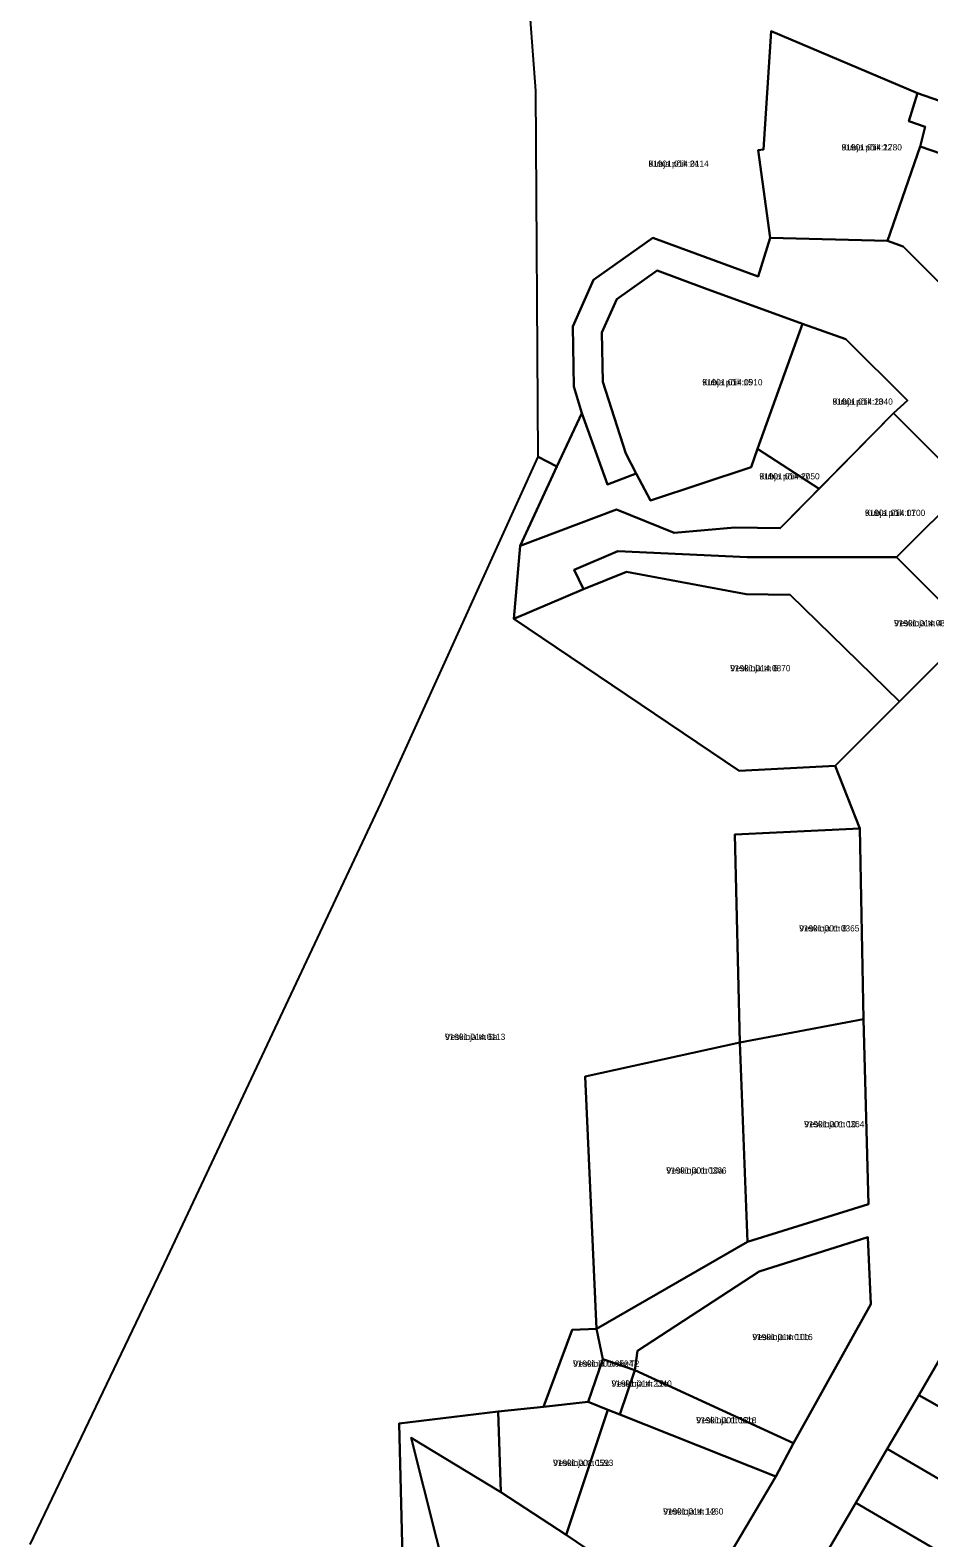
# Model space of a CAD drawing. Extents: x 675810 to 681273, y 6411190 to 6417565.
# Drawn here: x 678176.1 to 678392.3, y 6413180.1 to 6413542.7 of the extents above; entities that cross this region are included whole.
import ezdxf

# ---------------------------------------------------------------- set-up
doc = ezdxf.new("R2010")
doc.units = 0
for name, color, linetype in [('L_AADRESS', 7, 'Continuous'), ('PIIR', 7, 'Continuous'), ('TUNNUS', 7, 'Continuous')]:
    doc.layers.add(name, color=color, linetype=linetype)

msp = doc.modelspace()

# ---------------------------------------------------------------- linework, layer by layer
at = {"layer": 'PIIR'}
for points in [[(678295.76, 6413554.98), (678293.96, 6413581.95), (678477.82, 6413522.85), (678458.5, 6413494.01), (678446.21, 6413498.66), (678451.25, 6413506.22), (678426.9, 6413514.62), (678389.61, 6413527.56), (678354.34, 6413542.49), (678352.55, 6413514.04), (678351.25, 6413513.9), (678354.14, 6413492.79), (678351.28, 6413483.5), (678325.9, 6413492.81), (678311.61, 6413482.73), (678306.63, 6413471.48), (678306.92, 6413457.06), (678308.78, 6413450.62), (678302.83, 6413437.81), (678298.35, 6413440.16), (678297.78, 6413528.19)], [(678389.61, 6413527.56), (678387.5, 6413520.85), (678391.4, 6413519.53), (678390.19, 6413514.73), (678382.36, 6413492.05), (678354.14, 6413492.79), (678351.25, 6413513.9), (678352.55, 6413514.04), (678354.34, 6413542.49)], [(678426.9, 6413514.62), (678417.74, 6413505.28), (678390.19, 6413514.73), (678391.4, 6413519.53), (678387.5, 6413520.85), (678389.61, 6413527.56)], [(678386.16, 6413490.69), (678382.36, 6413492.05), (678390.19, 6413514.73), (678417.74, 6413505.28), (678408.5, 6413496.18), (678394.65, 6413482.21)], [(678338.31, 6413480.67), (678361.93, 6413472.14), (678351.11, 6413442.02), (678349.54, 6413437.63), (678325.34, 6413429.64), (678321.86, 6413436.1), (678319.44, 6413440.92), (678313.89, 6413458.18), (678313.65, 6413470.02), (678317.22, 6413478.07), (678326.94, 6413484.97)], [(678361.93, 6413472.14), (678372.33, 6413468.43), (678387.17, 6413453.67), (678383.8, 6413450.61), (678365.89, 6413432.45), (678351.11, 6413442.02)], [(678384.53, 6413415.96), (678354.7, 6413416.01), (678348.57, 6413416.03), (678317.48, 6413417.46), (678306.94, 6413412.98), (678309.26, 6413408.27), (678292.44, 6413401.19), (678293.98, 6413418.76), (678317.17, 6413427.45), (678331, 6413421.85), (678345.66, 6413423.1), (678356.55, 6413422.98), (678383.8, 6413450.61), (678401.49, 6413432.94)], [(678308.78, 6413450.62), (678314.99, 6413433.46), (678321.86, 6413436.1), (678325.34, 6413429.64), (678349.54, 6413437.63), (678351.11, 6413442.02), (678365.89, 6413432.45), (678356.55, 6413422.98), (678345.66, 6413423.1), (678331, 6413421.85), (678317.17, 6413427.45), (678293.98, 6413418.76), (678302.83, 6413437.81)], [(678402.22, 6413398.29), (678384.53, 6413415.96), (678401.49, 6413432.94), (678419.18, 6413415.28)], [(678348.37, 6413407.11), (678319.56, 6413412.48), (678309.26, 6413408.27), (678306.94, 6413412.98), (678317.48, 6413417.46), (678348.57, 6413416.03), (678354.7, 6413416.01), (678384.53, 6413415.96), (678402.22, 6413398.29), (678385.26, 6413381.3), (678358.97, 6413406.95)], [(678346.64, 6413364.6), (678292.44, 6413401.19), (678309.26, 6413408.27), (678319.56, 6413412.48), (678348.37, 6413407.11), (678358.97, 6413406.95), (678385.26, 6413381.3), (678369.78, 6413365.8)], [(678346.8, 6413299.26), (678345.6, 6413349.27), (678375.7, 6413350.7), (678376.58, 6413304.88)], [(678348.69, 6413251.36), (678346.8, 6413299.26), (678376.58, 6413304.88), (678377.8, 6413260.37)], [(678312.34, 6413230.42), (678309.59, 6413291.13), (678346.8, 6413299.26), (678348.69, 6413251.36)], [(678321.55, 6413220.47), (678322.24, 6413225.13), (678351.48, 6413244.23), (678377.66, 6413252.46), (678378.36, 6413236.35), (678359.77, 6413202.91)], [(678306.53, 6413230.15), (678312.34, 6413230.42), (678313.86, 6413223.09), (678310.38, 6413212.81), (678299.56, 6413211.68)], [(678397.45, 6413227.43), (678427.06, 6413210.73), (678419.68, 6413197.67), (678389.92, 6413214.47)], [(678321.55, 6413220.47), (678317.98, 6413209.79), (678315.07, 6413210.95), (678310.38, 6413212.81), (678313.86, 6413223.09)], [(678359.77, 6413202.91), (678355.48, 6413194.89), (678317.98, 6413209.79), (678321.55, 6413220.47)], [(678288.73, 6413210.5), (678299.56, 6413211.68), (678310.38, 6413212.81), (678315.07, 6413210.95), (678305.06, 6413180.85), (678289.3, 6413191.12)], [(678389.92, 6413214.47), (678419.68, 6413197.67), (678411.67, 6413184.37), (678382.31, 6413201.53)], [(678264.91, 6413207.66), (678288.73, 6413210.5), (678289.3, 6413191.12), (678267.76, 6413204.19), (678282.97, 6413143.7), (678276.6, 6413143.82), (678266.54, 6413143.9), (678266.34, 6413149.86)], [(678335.13, 6413160.53), (678305.06, 6413180.85), (678315.07, 6413210.95), (678317.98, 6413209.79), (678355.48, 6413194.89)], [(678435.46, 6413132.45), (678399.43, 6413154.72), (678395.78, 6413156.89), (678366.24, 6413174.06), (678374.74, 6413188.57), (678404.1, 6413171.42), (678411.67, 6413184.37), (678419.68, 6413197.67), (678427.06, 6413210.73), (678448.79, 6413198.47), (678468.34, 6413187.35)], [(678267.76, 6413204.19), (678289.3, 6413191.12), (678305.06, 6413180.85), (678335.13, 6413160.53), (678321.6, 6413137.39), (678312.36, 6413143.28), (678282.97, 6413143.7)], [(678382.31, 6413201.53), (678411.67, 6413184.37), (678404.1, 6413171.42), (678374.74, 6413188.57)]]:
    msp.add_lwpolyline(points, close=True, dxfattribs=at)
for points in [[(678401.49, 6413432.94), (678383.8, 6413450.61), (678387.17, 6413453.67), (678372.33, 6413468.43), (678361.93, 6413472.14), (678338.31, 6413480.67), (678326.94, 6413484.97), (678317.22, 6413478.07), (678313.65, 6413470.02), (678313.89, 6413458.18), (678319.44, 6413440.92), (678321.86, 6413436.1), (678314.99, 6413433.46), (678308.78, 6413450.62), (678306.92, 6413457.06), (678306.63, 6413471.48), (678311.61, 6413482.73), (678325.9, 6413492.81), (678351.28, 6413483.5), (678354.14, 6413492.79), (678382.36, 6413492.05), (678386.16, 6413490.69), (678394.65, 6413482.21)], [(678176.1, 6413178.55), (678207.8, 6413244.78), (678260.44, 6413356.78), (678298.35, 6413440.16), (678302.83, 6413437.81), (678293.98, 6413418.76), (678292.44, 6413401.19), (678346.64, 6413364.6), (678369.78, 6413365.8), (678375.7, 6413350.7), (678345.6, 6413349.27), (678346.8, 6413299.26), (678309.59, 6413291.13), (678312.34, 6413230.42), (678306.53, 6413230.15), (678299.56, 6413211.68), (678288.73, 6413210.5), (678264.91, 6413207.66), (678266.34, 6413149.86)], [(678335.13, 6413160.53), (678355.48, 6413194.89), (678359.77, 6413202.91), (678378.36, 6413236.35), (678377.66, 6413252.46), (678351.48, 6413244.23), (678322.24, 6413225.13), (678321.55, 6413220.47), (678313.86, 6413223.09), (678312.34, 6413230.42), (678348.69, 6413251.36), (678377.8, 6413260.37), (678376.58, 6413304.88), (678375.7, 6413350.7), (678369.78, 6413365.8), (678385.26, 6413381.3), (678402.22, 6413398.29)], [(678397.45, 6413227.43), (678389.92, 6413214.47), (678382.31, 6413201.53), (678374.74, 6413188.57), (678366.24, 6413174.06)]]:
    msp.add_lwpolyline(points, dxfattribs=at)

# ---------------------------------------------------------------- texts
at = {"layer": 'L_AADRESS'}
for s, p in [('Kubja põik 22', (678371.32, 6413513.82)), ('Kubja põik 24', (678324.85, 6413509.88)), ('Kubja põik 15', (678337.79, 6413457.31)), ('Kubja põik 13', (678369.14, 6413452.66)), ('Kubja põik 17', (678351.53, 6413434.69)), ('Kubja põik 11', (678376.94, 6413425.9)), ('Veskioja tn 4', (678383.93, 6413399.38)), ('Veskioja tn 6', (678344.51, 6413388.54)), ('Veskioja tn 8', (678361.09, 6413325.98)), ('Veskioja tn 6a', (678275.9, 6413299.88)), ('Veskioja tn 10', (678362.3, 6413278.88)), ('Veskioja tn 10a', (678329.14, 6413267.75)), ('Veskioja tn 10b', (678349.85, 6413227.69)), ('Veskioja tänav T2', (678306.71, 6413221.29)), ('Veskioja tn 12a', (678315.96, 6413216.48)), ('Veskioja tn 12b', (678336.34, 6413207.68)), ('Veskioja tn 12c', (678301.9, 6413197.42)), ('Veskioja tn 12', (678328.37, 6413185.74))]:
    msp.add_text(s, height=1.5, dxfattribs=at).set_placement(p)
at = {"layer": 'TUNNUS'}
for s, p in [('91901:014:1780', (678371.32, 6413513.82)), ('91901:014:0114', (678324.85, 6413509.88)), ('91901:014:0910', (678337.79, 6413457.31)), ('91901:014:2040', (678369.14, 6413452.66)), ('91901:014:2050', (678351.53, 6413434.69)), ('91901:014:0700', (678376.94, 6413425.9)), ('91901:014:0860', (678383.93, 6413399.38)), ('91901:014:0870', (678344.51, 6413388.54)), ('91901:001:0365', (678361.09, 6413325.98)), ('91901:014:0113', (678275.9, 6413299.88)), ('91901:001:0364', (678362.3, 6413278.88)), ('91901:001:0366', (678329.14, 6413267.75)), ('91901:014:0116', (678349.85, 6413227.69)), ('91901:001:0594', (678306.71, 6413221.29)), ('91901:014:2340', (678315.96, 6413216.48)), ('91901:001:0618', (678336.34, 6413207.68)), ('91901:001:0593', (678301.9, 6413197.42)), ('91901:014:1460', (678328.37, 6413185.74))]:
    msp.add_text(s, height=1.5, dxfattribs=at).set_placement(p)

doc.saveas('drawing.dxf')
